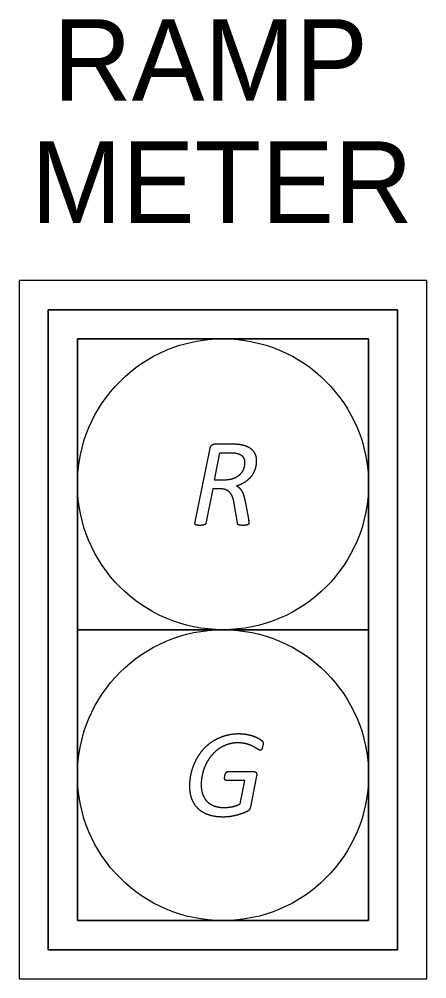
# Model space of a CAD drawing. Extents: x -30.3 to 21.6, y 6.6 to 27.2.
# Drawn here: x 15.424 to 16.124, y 9.926 to 11.575 of the extents above; entities that cross this region are included whole.
import ezdxf

# ---------------------------------------------------------------- set-up
doc = ezdxf.new("R2010")
doc.units = 0
doc.layers.add('UT_X_Water', color=7, linetype='Continuous')
doc.layers.add('VG_X_Cells', color=7, linetype='Continuous')

msp = doc.modelspace()

# ---------------------------------------------------------------- linework, layer by layer
at = {"layer": 'VG_X_Cells'}
for p, q in [((15.7262, 10.7088), (15.7521, 10.838)), ((15.7262, 10.7088), (15.7521, 10.838)), ((15.7612, 10.8455), (15.7914, 10.8455)), ((15.7612, 10.8455), (15.7914, 10.8455)), ((15.8115, 10.8135), (15.8115, 10.8135)), ((15.799, 10.71), (15.7936, 10.7428)), ((15.799, 10.71), (15.7936, 10.7428)), ((15.8122, 10.747), (15.818, 10.7162)), ((15.8122, 10.747), (15.818, 10.7162)), ((15.7828, 10.2824), (15.827, 10.2824)), ((15.7828, 10.2824), (15.827, 10.2824)), ((15.832, 10.2749), (15.8213, 10.2212)), ((15.832, 10.2749), (15.8213, 10.2212))]:
    msp.add_line(p, q, dxfattribs=at)
for points in [[(15.4243, 9.9262), (16.1243, 9.9262), (16.1243, 11.1262), (15.4243, 11.1262)], [(15.4743, 11.0762), (16.0743, 11.0762), (16.0743, 9.9762), (15.4743, 9.9762)], [(15.4743, 9.9762), (16.0743, 9.9762), (16.0743, 11.0762), (15.4743, 11.0762)], [(15.5243, 11.0262), (16.0243, 11.0262), (16.0243, 10.0262), (15.5243, 10.0262)], [(15.5243, 10.5262), (16.0243, 10.5262), (16.0243, 11.0262), (15.5243, 11.0262)], [(15.5243, 10.0262), (16.0243, 10.0262), (16.0243, 10.5262), (15.5243, 10.5262)]]:
    msp.add_lwpolyline(points, close=True, dxfattribs=at)
for points in [[(15.776, 10.7833), (15.7597, 10.7833), (15.7691, 10.8303), (15.7884, 10.8303)], [(15.769, 10.7683), (15.7567, 10.7683), (15.7447, 10.7088)], [(15.769, 10.7683), (15.7567, 10.7683), (15.7447, 10.7088)], [(15.8039, 10.2268), (15.8119, 10.2672), (15.7798, 10.2672)], [(15.8039, 10.2268), (15.8119, 10.2672), (15.7798, 10.2672)]]:
    msp.add_lwpolyline(points, dxfattribs=at)
for centre in [(15.7743, 10.7762), (15.7743, 10.2762)]:
    msp.add_circle(centre, 0.25, dxfattribs=at)
for points in [[(15.7521, 10.838), (15.753, 10.8422), (15.7555, 10.8438)], [(15.7521, 10.838), (15.753, 10.8422), (15.7555, 10.8438)], [(15.7555, 10.8438), (15.7581, 10.8455), (15.7612, 10.8455)], [(15.7555, 10.8438), (15.7581, 10.8455), (15.7612, 10.8455)], [(15.7914, 10.8455), (15.8014, 10.8455), (15.8088, 10.8436)], [(15.7914, 10.8455), (15.8014, 10.8455), (15.8088, 10.8436)], [(15.8088, 10.8436), (15.8163, 10.8416), (15.8214, 10.8379)], [(15.8088, 10.8436), (15.8163, 10.8416), (15.8214, 10.8379)], [(15.8214, 10.8379), (15.8264, 10.8342), (15.829, 10.8288)], [(15.8214, 10.8379), (15.8264, 10.8342), (15.829, 10.8288)], [(15.7884, 10.8303), (15.7945, 10.8303), (15.799, 10.8291)], [(15.799, 10.8291), (15.8035, 10.8279), (15.8062, 10.8256)], [(15.8062, 10.8256), (15.8089, 10.8234), (15.8102, 10.8202)], [(15.8102, 10.8202), (15.8115, 10.8171), (15.8115, 10.8135)], [(15.829, 10.8288), (15.8315, 10.8233), (15.8315, 10.8163)], [(15.829, 10.8288), (15.8315, 10.8233), (15.8315, 10.8163)], [(15.8115, 10.8135), (15.8115, 10.8078), (15.8095, 10.8024)], [(15.8315, 10.8163), (15.8315, 10.8089), (15.8294, 10.8022)], [(15.8315, 10.8163), (15.8315, 10.8089), (15.8294, 10.8022)], [(15.8033, 10.7927), (15.7991, 10.7885), (15.7923, 10.7859)], [(15.8095, 10.8024), (15.8075, 10.797), (15.8033, 10.7927)], [(15.8231, 10.79), (15.8188, 10.7844), (15.8124, 10.78)], [(15.8231, 10.79), (15.8188, 10.7844), (15.8124, 10.78)], [(15.8294, 10.8022), (15.8273, 10.7956), (15.8231, 10.79)], [(15.8294, 10.8022), (15.8273, 10.7956), (15.8231, 10.79)], [(15.7923, 10.7859), (15.7856, 10.7833), (15.776, 10.7833)], [(15.8124, 10.78), (15.806, 10.7757), (15.7975, 10.773)], [(15.8124, 10.78), (15.806, 10.7757), (15.7975, 10.773)], [(15.7975, 10.773), (15.8032, 10.7709), (15.8067, 10.7644)], [(15.7975, 10.773), (15.8032, 10.7709), (15.8067, 10.7644)], [(15.7796, 10.7665), (15.7753, 10.7683), (15.769, 10.7683)], [(15.7796, 10.7665), (15.7753, 10.7683), (15.769, 10.7683)], [(15.7868, 10.7612), (15.784, 10.7646), (15.7796, 10.7665)], [(15.7868, 10.7612), (15.784, 10.7646), (15.7796, 10.7665)], [(15.7911, 10.7531), (15.7896, 10.7578), (15.7868, 10.7612)], [(15.7911, 10.7531), (15.7896, 10.7578), (15.7868, 10.7612)], [(15.8067, 10.7644), (15.8103, 10.7578), (15.8122, 10.747)], [(15.8067, 10.7644), (15.8103, 10.7578), (15.8122, 10.747)], [(15.7936, 10.7428), (15.7927, 10.7485), (15.7911, 10.7531)], [(15.7936, 10.7428), (15.7927, 10.7485), (15.7911, 10.7531)], [(15.7264, 10.7073), (15.726, 10.708), (15.7262, 10.7088)], [(15.7264, 10.7073), (15.726, 10.708), (15.7262, 10.7088)], [(15.7277, 10.7063), (15.7267, 10.7067), (15.7264, 10.7073)], [(15.7277, 10.7063), (15.7267, 10.7067), (15.7264, 10.7073)], [(15.7305, 10.7057), (15.7287, 10.7059), (15.7277, 10.7063)], [(15.7305, 10.7057), (15.7287, 10.7059), (15.7277, 10.7063)], [(15.7347, 10.7055), (15.7322, 10.7055), (15.7305, 10.7057)], [(15.7347, 10.7055), (15.7322, 10.7055), (15.7305, 10.7057)], [(15.7392, 10.7058), (15.7374, 10.7055), (15.7347, 10.7055)], [(15.7392, 10.7058), (15.7374, 10.7055), (15.7347, 10.7055)], [(15.7423, 10.7064), (15.7411, 10.706), (15.7392, 10.7058)], [(15.7423, 10.7064), (15.7411, 10.706), (15.7392, 10.7058)], [(15.744, 10.7074), (15.7434, 10.7068), (15.7423, 10.7064)], [(15.744, 10.7074), (15.7434, 10.7068), (15.7423, 10.7064)], [(15.7447, 10.7088), (15.7445, 10.7081), (15.744, 10.7074)], [(15.7447, 10.7088), (15.7445, 10.7081), (15.744, 10.7074)], [(15.7996, 10.7078), (15.7993, 10.7086), (15.799, 10.71)], [(15.7996, 10.7078), (15.7993, 10.7086), (15.799, 10.71)], [(15.8009, 10.7065), (15.8, 10.707), (15.7996, 10.7078)], [(15.8009, 10.7065), (15.8, 10.707), (15.7996, 10.7078)], [(15.8036, 10.7057), (15.8019, 10.7059), (15.8009, 10.7065)], [(15.8036, 10.7057), (15.8019, 10.7059), (15.8009, 10.7065)], [(15.8082, 10.7055), (15.8053, 10.7055), (15.8036, 10.7057)], [(15.8082, 10.7055), (15.8053, 10.7055), (15.8036, 10.7057)], [(15.8132, 10.7057), (15.8111, 10.7055), (15.8082, 10.7055)], [(15.8132, 10.7057), (15.8111, 10.7055), (15.8082, 10.7055)], [(15.8165, 10.7064), (15.8153, 10.7059), (15.8132, 10.7057)], [(15.8165, 10.7064), (15.8153, 10.7059), (15.8132, 10.7057)], [(15.8182, 10.7075), (15.8177, 10.7068), (15.8165, 10.7064)], [(15.8182, 10.7075), (15.8177, 10.7068), (15.8165, 10.7064)], [(15.818, 10.7162), (15.8183, 10.7141), (15.8185, 10.7123)], [(15.818, 10.7162), (15.8183, 10.7141), (15.8185, 10.7123)], [(15.8188, 10.7092), (15.8188, 10.7082), (15.8182, 10.7075)], [(15.8188, 10.7092), (15.8188, 10.7082), (15.8182, 10.7075)], [(15.8185, 10.7123), (15.8188, 10.7106), (15.8188, 10.7092)], [(15.8185, 10.7123), (15.8188, 10.7106), (15.8188, 10.7092)], [(15.7564, 10.3342), (15.7659, 10.3404), (15.7772, 10.3439)], [(15.7564, 10.3342), (15.7659, 10.3404), (15.7772, 10.3439)], [(15.7772, 10.3439), (15.7885, 10.3475), (15.8016, 10.3475)], [(15.7772, 10.3439), (15.7885, 10.3475), (15.8016, 10.3475)], [(15.8016, 10.3475), (15.8092, 10.3475), (15.8157, 10.3461)], [(15.8016, 10.3475), (15.8092, 10.3475), (15.8157, 10.3461)], [(15.8157, 10.3461), (15.8223, 10.3448), (15.8275, 10.3429)], [(15.8157, 10.3461), (15.8223, 10.3448), (15.8275, 10.3429)], [(15.8275, 10.3429), (15.8326, 10.341), (15.8362, 10.3388)], [(15.8275, 10.3429), (15.8326, 10.341), (15.8362, 10.3388)], [(15.7397, 10.3196), (15.747, 10.3281), (15.7564, 10.3342)], [(15.7397, 10.3196), (15.747, 10.3281), (15.7564, 10.3342)], [(15.7819, 10.3288), (15.7735, 10.326), (15.7665, 10.321)], [(15.7819, 10.3288), (15.7735, 10.326), (15.7665, 10.321)], [(15.7998, 10.3317), (15.7902, 10.3317), (15.7819, 10.3288)], [(15.7998, 10.3317), (15.7902, 10.3317), (15.7819, 10.3288)], [(15.8155, 10.3297), (15.809, 10.3317), (15.7998, 10.3317)], [(15.8155, 10.3297), (15.809, 10.3317), (15.7998, 10.3317)], [(15.8267, 10.3253), (15.8221, 10.3277), (15.8155, 10.3297)], [(15.8267, 10.3253), (15.8221, 10.3277), (15.8155, 10.3297)], [(15.834, 10.3209), (15.8312, 10.3228), (15.8267, 10.3253)], [(15.834, 10.3209), (15.8312, 10.3228), (15.8267, 10.3253)], [(15.8362, 10.3388), (15.8398, 10.3365), (15.8411, 10.3353)], [(15.8362, 10.3388), (15.8398, 10.3365), (15.8411, 10.3353)], [(15.8411, 10.3353), (15.8423, 10.3341), (15.8428, 10.3331)], [(15.8411, 10.3353), (15.8423, 10.3341), (15.8428, 10.3331)], [(15.8426, 10.3261), (15.8423, 10.3249), (15.8419, 10.3235)], [(15.8426, 10.3261), (15.8423, 10.3249), (15.8419, 10.3235)], [(15.843, 10.3285), (15.8429, 10.3273), (15.8426, 10.3261)], [(15.843, 10.3285), (15.8429, 10.3273), (15.8426, 10.3261)], [(15.8428, 10.3331), (15.8432, 10.332), (15.8432, 10.3304)], [(15.8428, 10.3331), (15.8432, 10.332), (15.8432, 10.3304)], [(15.8432, 10.3304), (15.8432, 10.3296), (15.843, 10.3285)], [(15.8432, 10.3304), (15.8432, 10.3296), (15.843, 10.3285)], [(15.7275, 10.301), (15.7325, 10.3111), (15.7397, 10.3196)], [(15.7275, 10.301), (15.7325, 10.3111), (15.7397, 10.3196)], [(15.754, 10.3091), (15.7485, 10.3023), (15.7447, 10.2943)], [(15.754, 10.3091), (15.7485, 10.3023), (15.7447, 10.2943)], [(15.7665, 10.321), (15.7595, 10.316), (15.754, 10.3091)], [(15.7665, 10.321), (15.7595, 10.316), (15.754, 10.3091)], [(15.8384, 10.319), (15.8367, 10.319), (15.834, 10.3209)], [(15.8384, 10.319), (15.8367, 10.319), (15.834, 10.3209)], [(15.8398, 10.3195), (15.8391, 10.319), (15.8384, 10.319)], [(15.8398, 10.3195), (15.8391, 10.319), (15.8384, 10.319)], [(15.8409, 10.3212), (15.8404, 10.3201), (15.8398, 10.3195)], [(15.8409, 10.3212), (15.8404, 10.3201), (15.8398, 10.3195)], [(15.8419, 10.3235), (15.8415, 10.3222), (15.8409, 10.3212)], [(15.8419, 10.3235), (15.8415, 10.3222), (15.8409, 10.3212)], [(15.7199, 10.2799), (15.7226, 10.291), (15.7275, 10.301)], [(15.7199, 10.2799), (15.7226, 10.291), (15.7275, 10.301)], [(15.7447, 10.2943), (15.7408, 10.2862), (15.7389, 10.2774)], [(15.7447, 10.2943), (15.7408, 10.2862), (15.7389, 10.2774)], [(15.7173, 10.2572), (15.7173, 10.2687), (15.7199, 10.2799)], [(15.7173, 10.2572), (15.7173, 10.2687), (15.7199, 10.2799)], [(15.7389, 10.2774), (15.7369, 10.2686), (15.7369, 10.2595)], [(15.7389, 10.2774), (15.7369, 10.2686), (15.7369, 10.2595)], [(15.7772, 10.2727), (15.7774, 10.274), (15.7777, 10.2753)], [(15.7772, 10.2727), (15.7774, 10.274), (15.7777, 10.2753)], [(15.7777, 10.2753), (15.7779, 10.2766), (15.7784, 10.2779)], [(15.7777, 10.2753), (15.7779, 10.2766), (15.7784, 10.2779)], [(15.7784, 10.2779), (15.7789, 10.2792), (15.7796, 10.2802)], [(15.7784, 10.2779), (15.7789, 10.2792), (15.7796, 10.2802)], [(15.7796, 10.2802), (15.7802, 10.2812), (15.781, 10.2818)], [(15.7796, 10.2802), (15.7802, 10.2812), (15.781, 10.2818)], [(15.781, 10.2818), (15.7818, 10.2824), (15.7828, 10.2824)], [(15.781, 10.2818), (15.7818, 10.2824), (15.7828, 10.2824)], [(15.827, 10.2824), (15.83, 10.2824), (15.8314, 10.2804)], [(15.827, 10.2824), (15.83, 10.2824), (15.8314, 10.2804)], [(15.8314, 10.2804), (15.8327, 10.2783), (15.832, 10.2749)], [(15.8314, 10.2804), (15.8327, 10.2783), (15.832, 10.2749)], [(15.7369, 10.2595), (15.7369, 10.25), (15.7396, 10.2427)], [(15.7369, 10.2595), (15.7369, 10.25), (15.7396, 10.2427)], [(15.7771, 10.2707), (15.7771, 10.2715), (15.7772, 10.2727)], [(15.7771, 10.2707), (15.7771, 10.2715), (15.7772, 10.2727)], [(15.7778, 10.2681), (15.7771, 10.269), (15.7771, 10.2707)], [(15.7778, 10.2681), (15.7771, 10.269), (15.7771, 10.2707)], [(15.7798, 10.2672), (15.7785, 10.2672), (15.7778, 10.2681)], [(15.7798, 10.2672), (15.7785, 10.2672), (15.7778, 10.2681)], [(15.721, 10.235), (15.7173, 10.2448), (15.7173, 10.2572)], [(15.721, 10.235), (15.7173, 10.2448), (15.7173, 10.2572)], [(15.7396, 10.2427), (15.7424, 10.2355), (15.7475, 10.2305)], [(15.7396, 10.2427), (15.7424, 10.2355), (15.7475, 10.2305)], [(15.732, 10.2183), (15.7248, 10.2252), (15.721, 10.235)], [(15.732, 10.2183), (15.7248, 10.2252), (15.721, 10.235)], [(15.7475, 10.2305), (15.7527, 10.2256), (15.76, 10.223)], [(15.7475, 10.2305), (15.7527, 10.2256), (15.76, 10.223)], [(15.7904, 10.222), (15.7977, 10.2236), (15.8039, 10.2268)], [(15.7904, 10.222), (15.7977, 10.2236), (15.8039, 10.2268)], [(15.7499, 10.2078), (15.7392, 10.2114), (15.732, 10.2183)], [(15.7499, 10.2078), (15.7392, 10.2114), (15.732, 10.2183)], [(15.76, 10.223), (15.7674, 10.2205), (15.7764, 10.2205)], [(15.76, 10.223), (15.7674, 10.2205), (15.7764, 10.2205)], [(15.7764, 10.2205), (15.7831, 10.2205), (15.7904, 10.222)], [(15.7764, 10.2205), (15.7831, 10.2205), (15.7904, 10.222)], [(15.8137, 10.2129), (15.8097, 10.211), (15.8037, 10.209)], [(15.8137, 10.2129), (15.8097, 10.211), (15.8037, 10.209)], [(15.8186, 10.2157), (15.8176, 10.2147), (15.8137, 10.2129)], [(15.8186, 10.2157), (15.8176, 10.2147), (15.8137, 10.2129)], [(15.8201, 10.2179), (15.8194, 10.2167), (15.8186, 10.2157)], [(15.8201, 10.2179), (15.8194, 10.2167), (15.8186, 10.2157)], [(15.8213, 10.2212), (15.8208, 10.2192), (15.8201, 10.2179)], [(15.8213, 10.2212), (15.8208, 10.2192), (15.8201, 10.2179)], [(15.7746, 10.2042), (15.7606, 10.2042), (15.7499, 10.2078)], [(15.7746, 10.2042), (15.7606, 10.2042), (15.7499, 10.2078)], [(15.7903, 10.2056), (15.7828, 10.2042), (15.7746, 10.2042)], [(15.7903, 10.2056), (15.7828, 10.2042), (15.7746, 10.2042)], [(15.8037, 10.209), (15.7978, 10.2071), (15.7903, 10.2056)], [(15.8037, 10.209), (15.7978, 10.2071), (15.7903, 10.2056)]]:
    msp.add_open_spline(points, degree=2, dxfattribs=at)

# ---------------------------------------------------------------- texts
at = {"layer": 'UT_X_Water'}
for s, p in [('RAMP', (15.4824, 11.4354)), ('METER', (15.4448, 11.2254))]:
    msp.add_text(s, height=0.14, dxfattribs=at).set_placement(p)

doc.saveas('drawing.dxf')
